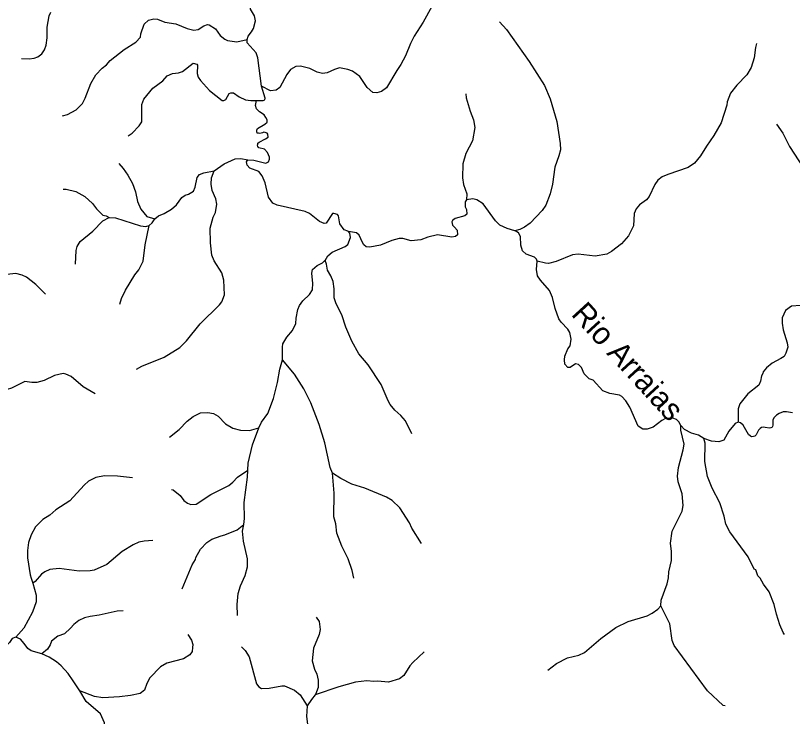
# Model space of a CAD drawing. Extents: x 500 to 555.2, y 9115.7 to 9171.
# Drawn here: x 511.43 to 518.44, y 9120.08 to 9126.41 of the extents above; entities that cross this region are included whole.
import ezdxf
from ezdxf.enums import TextEntityAlignment as Align

# ---------------------------------------------------------------- set-up
doc = ezdxf.new("R2010")
doc.units = 0
doc.header["$LTSCALE"] = 0.064
doc.layers.add('61', color=7, linetype='Continuous')
doc.layers.add('7', color=7, linetype='Continuous', lineweight=25)

msp = doc.modelspace()

# ---------------------------------------------------------------- linework, layer by layer
at = {"layer": '7'}
for points in [[(513.5153, 9126.1907), (513.524, 9126.2197), (513.5567, 9126.2587), (513.5731, 9126.2883), (513.5911, 9126.3571), (513.5813, 9126.403), (513.5472, 9126.4633), (513.5455, 9126.498), (513.5603, 9126.5225), (513.5851, 9126.5309), (513.639, 9126.5082), (513.6725, 9126.511), (513.6954, 9126.5417), (513.707, 9126.578)], [(515.1839, 9126.4888), (515.105, 9126.3473), (515.0234, 9126.2198), (514.9899, 9126.1526), (514.9459, 9126.0422), (514.9049, 9125.9635), (514.8666, 9125.9091), (514.7738, 9125.7535), (514.729, 9125.7221), (514.6854, 9125.7091), (514.6515, 9125.7124), (514.5984, 9125.7555), (514.5325, 9125.8567), (514.4663, 9125.9029), (514.4238, 9125.9193), (514.3503, 9125.9334), (514.3057, 9125.9205), (514.2375, 9125.8881), (514.1961, 9125.8847), (514.1494, 9125.8961), (514.0818, 9125.9294), (513.9985, 9125.9501), (513.9571, 9125.9453), (513.9078, 9125.9192), (513.8736, 9125.8749), (513.811, 9125.7568), (513.7769, 9125.734), (513.7276, 9125.7275), (513.6466, 9125.7683)], [(511.4793, 9126.0192), (511.5479, 9126.0143), (511.5926, 9126.0206), (511.6256, 9126.0337), (511.6621, 9126.0619), (511.6867, 9126.0955), (511.7029, 9126.1402), (511.7113, 9126.2062), (511.7098, 9126.3008), (511.7301, 9126.4028), (511.744, 9126.4358)], [(511.8491, 9125.5007), (511.8952, 9125.5134), (511.9728, 9125.5544), (512.0291, 9125.612), (512.0555, 9125.6611), (512.1049, 9125.7923), (512.1494, 9125.8716), (512.2079, 9125.9318), (512.2479, 9125.962), (512.279, 9126.001), (512.4076, 9126.1005), (512.5121, 9126.1658), (512.5544, 9126.2119), (512.5579, 9126.2423), (512.586, 9126.3291), (512.6273, 9126.3638), (512.6754, 9126.3751), (512.7075, 9126.3721), (512.7737, 9126.3474), (512.8739, 9126.3322), (512.9748, 9126.2887), (513.034, 9126.2751), (513.0738, 9126.2804), (513.1265, 9126.3133), (513.1576, 9126.324), (513.1745, 9126.3225), (513.2292, 9126.2873), (513.2734, 9126.2256), (513.314, 9126.1925), (513.3386, 9126.1801), (513.4219, 9126.1701), (513.5153, 9126.1907)], [(515.7935, 9126.3494), (515.8576, 9126.2788), (516.0617, 9125.9924), (516.1991, 9125.7748), (516.2525, 9125.6558), (516.3109, 9125.451), (516.3404, 9125.2522), (516.3434, 9125.1959), (516.331, 9125.1393), (516.2942, 9125.0377), (516.2716, 9124.8856), (516.2501, 9124.7962), (516.2125, 9124.6961), (516.1785, 9124.6468), (516.0701, 9124.5338), (516.0207, 9124.4955), (515.9786, 9124.4752), (515.9329, 9124.4649)], [(513.6466, 9125.7683), (513.6142, 9126.0251), (513.5971, 9126.0689), (513.5179, 9126.1597), (513.5153, 9126.1907)], [(518.1147, 9126.1532), (518.1045, 9126.1172), (518.0936, 9126.0252), (518.0664, 9125.9382), (518.0268, 9125.8704), (517.9353, 9125.7787), (517.8776, 9125.7047), (517.848, 9125.6261), (517.8459, 9125.5988), (517.7951, 9125.4386), (517.7296, 9125.3238), (517.6624, 9125.2286), (517.6097, 9125.1389), (517.5529, 9125.0732), (517.4955, 9125.0338), (517.314, 9124.9724), (517.2632, 9124.9494), (517.2244, 9124.9218), (517.1971, 9124.8819), (517.1452, 9124.7737), (517.121, 9124.7431), (517.0575, 9124.6975), (517.0274, 9124.6627), (517.0093, 9124.6204), (517.0028, 9124.5091), (516.9574, 9124.4188), (516.8963, 9124.3461), (516.8053, 9124.2761), (516.7635, 9124.2543), (516.6571, 9124.2346), (516.5035, 9124.2525), (516.4542, 9124.2464), (516.3064, 9124.1861), (516.2367, 9124.1691), (516.2084, 9124.1708), (516.1328, 9124.1909)], [(512.4426, 9125.3219), (512.4792, 9125.3455), (512.543, 9125.4107), (512.5658, 9125.4474), (512.5664, 9125.6036), (512.5851, 9125.6504), (512.6645, 9125.75), (512.7538, 9125.8166), (512.7958, 9125.8614), (512.8424, 9125.8818), (512.8963, 9125.8881), (512.9328, 9125.9008), (513.029, 9125.9761), (513.0608, 9125.9682), (513.0691, 9125.9587), (513.0666, 9125.8827), (513.0744, 9125.8493), (513.0951, 9125.8188), (513.1762, 9125.7306), (513.2906, 9125.6406), (513.3063, 9125.6402), (513.3242, 9125.6481), (513.3536, 9125.7038), (513.3701, 9125.7093), (513.3927, 9125.7076), (513.4441, 9125.6728), (513.502, 9125.6455), (513.5493, 9125.6381), (513.5999, 9125.6402)], [(513.5999, 9125.6402), (513.6612, 9125.6388), (513.6745, 9125.6455), (513.6802, 9125.6592), (513.6466, 9125.7683)], [(513.5233, 9125.1055), (513.5772, 9125.1018), (513.6856, 9125.0745), (513.7076, 9125.0862), (513.719, 9125.1102), (513.7172, 9125.129), (513.7008, 9125.1711), (513.6719, 9125.2002), (513.6222, 9125.2134), (513.6126, 9125.2244), (513.6097, 9125.2354), (513.6113, 9125.2455), (513.6139, 9125.2542), (513.6241, 9125.2645), (513.6824, 9125.2923), (513.706, 9125.3102), (513.7042, 9125.3364), (513.6955, 9125.3463), (513.6803, 9125.3512), (513.6673, 9125.353), (513.6536, 9125.3473), (513.6306, 9125.3431), (513.6191, 9125.3452), (513.6076, 9125.3463), (513.6043, 9125.3573), (513.6034, 9125.3724), (513.6111, 9125.3858), (513.6759, 9125.4248), (513.6961, 9125.4443), (513.6977, 9125.4657), (513.685, 9125.4865), (513.6693, 9125.5094), (513.6269, 9125.536), (513.6011, 9125.5652), (513.5915, 9125.5951), (513.5999, 9125.6402)], [(515.4895, 9125.6995), (515.494, 9125.6632), (515.5285, 9125.543), (515.5596, 9125.4643), (515.571, 9125.3956), (515.5494, 9125.276), (515.4909, 9125.1618), (515.463, 9125.0671), (515.4592, 9124.9422), (515.4693, 9124.8814), (515.5, 9124.7968), (515.4966, 9124.7429)], [(518.2954, 9125.4274), (518.3529, 9125.3434), (518.4123, 9125.2248), (518.5337, 9125.0361), (518.5639, 9124.9804), (518.5778, 9124.9196), (518.6115, 9124.8383), (518.6578, 9124.6847), (518.7217, 9124.5403), (518.7361, 9124.4723), (518.7348, 9124.3947), (518.7102, 9124.3225), (518.6475, 9124.2163), (518.5854, 9124.1454), (518.558, 9124.1033), (518.5447, 9124.0699), (518.535, 9123.9662), (518.543, 9123.8919), (518.5349, 9123.8409), (518.5111, 9123.7887)], [(513.2176, 9125.006), (513.3091, 9125.0695), (513.4079, 9125.1122), (513.4607, 9125.1172), (513.5233, 9125.1055)], [(514.4318, 9124.4585), (514.4262, 9124.4595), (514.3933, 9124.4727), (514.3522, 9124.5271), (514.3423, 9124.5996), (514.3319, 9124.6118), (514.2998, 9124.6214), (514.2875, 9124.6191), (514.228, 9124.5338), (514.2117, 9124.5302), (514.1699, 9124.5488), (514.0797, 9124.6191), (514.0412, 9124.6394), (513.7862, 9124.6951), (513.7482, 9124.7125), (513.7095, 9124.7659), (513.6793, 9124.8954), (513.6533, 9124.9596), (513.6221, 9125.0004), (513.5393, 9125.03), (513.516, 9125.0547), (513.5116, 9125.0867), (513.5233, 9125.1055)], [(512.3579, 9125.0696), (512.3967, 9125.027), (512.4403, 9124.9651), (512.4811, 9124.8913), (512.5084, 9124.8152), (512.5266, 9124.7272), (512.5575, 9124.6583), (512.6098, 9124.5943), (512.6824, 9124.5705)], [(512.5174, 9123.2153), (512.5667, 9123.2408), (512.7677, 9123.3243), (512.91, 9123.4108), (512.9682, 9123.4707), (513.0921, 9123.6239), (513.2667, 9123.7954), (513.2878, 9123.8218), (513.3122, 9123.8869), (513.3072, 9124.0186), (513.2876, 9124.0836), (513.2186, 9124.1941), (513.1976, 9124.243), (513.1844, 9124.3546), (513.1828, 9124.4866), (513.21, 9124.5869), (513.2302, 9124.6299), (513.2418, 9124.7037), (513.2332, 9124.7515), (513.1998, 9124.8262), (513.191, 9124.8861), (513.1958, 9124.9426), (513.2176, 9125.006)], [(512.6824, 9124.5705), (512.6831, 9124.5716), (512.7152, 9124.5996), (512.7661, 9124.6202), (512.8345, 9124.6603), (512.8787, 9124.6983), (512.9274, 9124.7631), (512.958, 9124.7839), (512.9874, 9124.7956), (513.0311, 9124.8203), (513.0482, 9124.8569), (513.0645, 9124.9437), (513.0852, 9124.9712), (513.1246, 9124.988), (513.2176, 9125.006)], [(511.8562, 9124.8381), (511.8831, 9124.8406), (511.97, 9124.817), (512.0505, 9124.7735), (512.1194, 9124.7107), (512.1552, 9124.6633), (512.2144, 9124.6059), (512.2437, 9124.5999), (512.2716, 9124.5829)], [(515.4966, 9124.7429), (515.4842, 9124.7265), (515.4841, 9124.6786), (515.4961, 9124.655), (515.4996, 9124.6143), (515.4826, 9124.5999), (515.3929, 9124.5758), (515.3701, 9124.5562), (515.3644, 9124.5438), (515.3685, 9124.5151), (515.3866, 9124.4952), (515.4134, 9124.4684), (515.415, 9124.4288), (515.3981, 9124.4132), (515.363, 9124.4053), (515.2335, 9124.4281), (515.1476, 9124.4056), (515.0832, 9124.382), (514.9964, 9124.3726), (514.9205, 9124.3951), (514.8877, 9124.3953), (514.8208, 9124.3771), (514.7202, 9124.3354), (514.6245, 9124.3151), (514.5918, 9124.3201), (514.5689, 9124.3364), (514.5588, 9124.3575), (514.5269, 9124.4244), (514.5032, 9124.4457), (514.4318, 9124.4585)], [(515.9329, 9124.4649), (515.8622, 9124.4853), (515.7983, 9124.5146), (515.7592, 9124.555), (515.6452, 9124.7062), (515.5903, 9124.7438), (515.5529, 9124.7511), (515.4976, 9124.7442), (515.4966, 9124.7429)], [(511.9672, 9124.1613), (511.9724, 9124.2851), (511.9816, 9124.3219), (512.0104, 9124.3678), (512.1221, 9124.4601), (512.2144, 9124.5523), (512.2716, 9124.5829)], [(512.2716, 9124.5829), (512.3281, 9124.5805), (512.5525, 9124.5099), (512.6032, 9124.5036), (512.6305, 9124.5109)], [(512.3656, 9123.8003), (512.3809, 9123.8528), (512.4181, 9123.929), (512.5018, 9124.0667), (512.5376, 9124.1128), (512.5767, 9124.19), (512.5959, 9124.3357), (512.6305, 9124.5109)], [(512.6305, 9124.5109), (512.6592, 9124.5351), (512.6824, 9124.5705)], [(514.2196, 9124.1956), (514.2458, 9124.2377), (514.2829, 9124.2719), (514.4014, 9124.3232), (514.4263, 9124.3389), (514.4491, 9124.4038), (514.4428, 9124.443), (514.4318, 9124.4585)], [(516.1328, 9124.1909), (516.1285, 9124.2075), (516.1088, 9124.2273), (516.0346, 9124.2534), (516.0026, 9124.2839), (515.9852, 9124.3347), (515.9837, 9124.4117), (515.9655, 9124.4451), (515.9364, 9124.4639), (515.9329, 9124.4649)], [(513.8348, 9123.2985), (513.834, 9123.4144), (513.8392, 9123.4445), (513.8746, 9123.5025), (513.9253, 9123.5648), (513.9568, 9123.6276), (513.9586, 9123.6746), (513.9748, 9123.755), (513.9883, 9123.7883), (514.0189, 9123.8323), (514.0795, 9123.8897), (514.1062, 9123.9319), (514.1094, 9123.99), (514.1014, 9124.0778), (514.1017, 9124.1005), (514.1075, 9124.1154), (514.1477, 9124.1501), (514.197, 9124.176), (514.2189, 9124.1944), (514.2196, 9124.1956)], [(515.0032, 9122.6327), (514.9444, 9122.7484), (514.9037, 9122.7972), (514.85, 9122.8446), (514.8071, 9122.8957), (514.7881, 9122.9301), (514.7274, 9123.077), (514.609, 9123.2548), (514.5258, 9123.3526), (514.4605, 9123.4668), (514.4075, 9123.5952), (514.3716, 9123.7069), (514.3192, 9123.8043), (514.3031, 9123.8579), (514.3014, 9123.9393), (514.2913, 9124.0055), (514.2718, 9124.0573), (514.242, 9124.108), (514.2338, 9124.1631), (514.2196, 9124.1956)], [(516.4289, 9123.545), (516.4098, 9123.5763), (516.3498, 9123.6381), (516.3308, 9123.6697), (516.2965, 9123.764), (516.2718, 9123.8624), (516.2467, 9123.9262), (516.1649, 9124.0197), (516.1384, 9124.0581), (516.1271, 9124.1158), (516.1328, 9124.1909)], [(511.6973, 9123.8926), (511.608, 9123.9803), (511.5244, 9124.0459), (511.4844, 9124.0641), (511.4273, 9124.0784), (511.2921, 9124.0624), (511.2582, 9124.0441), (511.2088, 9124.0295), (511.0656, 9124.0278), (511.0514, 9124.0214), (510.9935, 9124.0149), (510.9343, 9123.9871), (510.8076, 9123.8737), (510.708, 9123.8142), (510.6315, 9123.795), (510.494, 9123.8064)], [(518.5111, 9123.7887), (518.4311, 9123.7832), (518.3759, 9123.744), (518.3466, 9123.6789), (518.3464, 9123.6303), (518.3547, 9123.5713), (518.3905, 9123.4538), (518.3955, 9123.4133), (518.3902, 9123.3943), (518.379, 9123.3606), (518.3626, 9123.331), (518.3326, 9123.3126), (518.2556, 9123.2696), (518.2037, 9123.2258), (518.1737, 9123.1926), (518.1704, 9123.1762), (518.1578, 9123.1562), (518.1511, 9123.1067), (518.1358, 9123.0712), (518.0351, 9122.9932), (517.9635, 9122.9023), (517.9494, 9122.8585), (517.9484, 9122.7369)], [(517.4296, 9122.7079), (517.4139, 9122.7394), (517.3916, 9122.7598), (517.3578, 9122.7728), (517.2917, 9122.7697), (517.2589, 9122.7533), (517.1801, 9122.6927), (517.1267, 9122.6735), (517.0873, 9122.6734), (517.0444, 9122.7022), (516.9705, 9122.8726), (516.9334, 9122.9293), (516.8968, 9122.9677), (516.8776, 9122.9798), (516.7897, 9122.9962), (516.7259, 9123.0209), (516.64, 9123.1147), (516.604, 9123.1295), (516.5571, 9123.1736), (516.5337, 9123.2307), (516.5074, 9123.2583), (516.4814, 9123.2632), (516.4326, 9123.2312), (516.4122, 9123.2307), (516.3824, 9123.2591), (516.3797, 9123.2996), (516.3846, 9123.3318), (516.4122, 9123.3974), (516.4317, 9123.427), (516.4403, 9123.4867), (516.4289, 9123.545)], [(513.6203, 9122.6864), (513.6448, 9122.7367), (513.7024, 9122.8159), (513.7552, 9122.9493), (513.7911, 9123.0956), (513.811, 9123.2144), (513.8348, 9123.2985)], [(514.2875, 9122.278), (514.2667, 9122.3285), (514.2163, 9122.551), (514.1667, 9122.7163), (514.0897, 9122.9125), (514.0266, 9123.039), (513.9442, 9123.1711), (513.8348, 9123.2985)], [(512.1454, 9122.9926), (512.0366, 9123.0549), (511.9279, 9123.1485), (511.8787, 9123.1715), (511.8562, 9123.1748), (511.7764, 9123.1583), (511.6845, 9123.1124), (511.6176, 9123.0948), (511.5739, 9123.0942), (511.5081, 9123.1026), (511.3905, 9123.0423), (511.3505, 9123.0323), (511.2909, 9123.029), (511.2141, 9123.0353), (511.1006, 9123.0815), (511.0304, 9123.0942), (510.9831, 9123.1141), (510.9346, 9123.1223)], [(518.4392, 9122.8223), (518.3834, 9122.8299), (518.3541, 9122.8288), (518.3173, 9122.8155), (518.2956, 9122.7992), (518.2743, 9122.7805), (518.261, 9122.7584), (518.2609, 9122.7113), (518.2585, 9122.6986), (518.256, 9122.6923), (518.2525, 9122.6882), (518.2442, 9122.6848), (518.2304, 9122.6838), (518.1906, 9122.6894), (518.1732, 9122.6907), (518.1598, 9122.6877), (518.148, 9122.6811), (518.1318, 9122.6636), (518.1105, 9122.6231), (518.099, 9122.6106), (518.0863, 9122.6068), (518.0725, 9122.6044), (518.0582, 9122.6093), (518.0408, 9122.6251), (517.9942, 9122.7108), (517.9695, 9122.7311), (517.9484, 9122.7369)], [(512.8164, 9122.6003), (512.9025, 9122.67), (512.9756, 9122.7447), (513.0285, 9122.7894), (513.0955, 9122.8222), (513.162, 9122.8239), (513.2138, 9122.8141), (513.2532, 9122.7911), (513.3207, 9122.7219), (513.3881, 9122.6839), (513.4554, 9122.6652), (513.5382, 9122.6616), (513.6203, 9122.6864)], [(513.5227, 9122.3037), (513.5265, 9122.3668), (513.5632, 9122.5313), (513.6203, 9122.6864)], [(517.2498, 9121.0795), (517.2542, 9121.1299), (517.3078, 9121.2781), (517.3196, 9121.3319), (517.3235, 9121.3876), (517.3456, 9121.4873), (517.3458, 9121.5688), (517.336, 9121.6462), (517.3513, 9121.7525), (517.4419, 9121.9336), (517.4519, 9121.9835), (517.4414, 9122.0899), (517.4065, 9122.1973), (517.4016, 9122.2484), (517.4083, 9122.3292), (517.4523, 9122.4861), (517.4605, 9122.5379), (517.4301, 9122.6658), (517.4296, 9122.7079)], [(517.639, 9122.5893), (517.5905, 9122.6185), (517.5285, 9122.6367), (517.4625, 9122.67), (517.4296, 9122.7079)], [(517.9484, 9122.7369), (517.9211, 9122.7237), (517.8631, 9122.6559), (517.8192, 9122.5742), (517.7733, 9122.5582), (517.7083, 9122.5648), (517.639, 9122.5893)], [(518.3675, 9120.8214), (518.3544, 9120.8389), (518.3241, 9120.9068), (518.2939, 9121.0032), (518.2743, 9121.0913), (518.2269, 9121.2061), (518.1771, 9121.2744), (518.1462, 9121.328), (518.1267, 9121.3494), (518.1068, 9121.403), (518.0939, 9121.4107), (518.0373, 9121.5227), (517.8718, 9121.7462), (517.836, 9121.8174), (517.8208, 9121.888), (517.7837, 9122.0103), (517.7133, 9122.1416), (517.6706, 9122.2465), (517.6461, 9122.383), (517.6492, 9122.5477), (517.639, 9122.5893)], [(512.832, 9122.1287), (512.848, 9122.127), (512.9107, 9122.0755), (512.9455, 9122.0293), (512.9773, 9122.0052), (513.0092, 9121.9953), (513.0552, 9121.997), (513.1887, 9122.0854), (513.351, 9122.1662), (513.3885, 9122.1947), (513.4301, 9122.2396), (513.5227, 9122.3037)], [(513.4864, 9121.8126), (513.4914, 9121.868), (513.4899, 9122.0107), (513.5189, 9122.2401), (513.5227, 9122.3037)], [(515.0905, 9121.6419), (515.0028, 9121.7819), (514.9803, 9121.8299), (514.8931, 9121.9632), (514.8241, 9122.0304), (514.7749, 9122.0614), (514.5792, 9122.1429), (514.4626, 9122.1782), (514.361, 9122.2292), (514.2875, 9122.278)], [(514.4781, 9121.3282), (514.4635, 9121.398), (514.4293, 9121.5051), (514.3707, 9121.6194), (514.3244, 9121.7348), (514.3159, 9121.8181), (514.2998, 9121.8824), (514.3014, 9122.0962), (514.2875, 9122.278)], [(512.4814, 9122.2356), (512.3458, 9122.2497), (512.2297, 9122.2531), (512.151, 9122.2366), (512.0855, 9122.2038), (512.0456, 9122.169), (511.9147, 9122.0284), (511.7894, 9121.9453), (511.7364, 9121.8975), (511.6716, 9121.8574), (511.6065, 9121.7922), (511.5673, 9121.7205), (511.5437, 9121.6498), (511.5343, 9121.5786), (511.5342, 9121.5138), (511.5568, 9121.359), (511.5656, 9121.3282), (511.5824, 9121.2839)], [(512.9299, 9121.232), (513.0188, 9121.4492), (513.0495, 9121.4987), (513.0532, 9121.5164), (513.0966, 9121.5914), (513.1523, 9121.6517), (513.1987, 9121.6811), (513.2807, 9121.7121), (513.3134, 9121.7189), (513.4265, 9121.7657), (513.4864, 9121.8126)], [(513.4294, 9120.992), (513.4256, 9121.0931), (513.4354, 9121.1895), (513.4561, 9121.2587), (513.4988, 9121.353), (513.5197, 9121.4318), (513.5203, 9121.504), (513.4832, 9121.6639), (513.4747, 9121.7534), (513.4864, 9121.8126)], [(512.6661, 9121.6692), (512.5879, 9121.6627), (512.5387, 9121.6528), (512.4884, 9121.6311), (512.3868, 9121.5712), (512.2511, 9121.4528), (512.1342, 9121.4028), (512.0985, 9121.3954), (511.9996, 9121.3936), (511.8196, 9121.4165), (511.7356, 9121.4069), (511.6899, 9121.3878), (511.6592, 9121.3661), (511.6014, 9121.2985), (511.5824, 9121.2839)], [(511.5824, 9121.2839), (511.6128, 9121.1745), (511.6128, 9121.1148), (511.5801, 9121.023), (511.4995, 9120.8776), (511.4289, 9120.7954)], [(516.2291, 9120.4982), (516.3084, 9120.559), (516.4087, 9120.6098), (516.509, 9120.6351), (516.5601, 9120.6588), (516.7088, 9120.7858), (516.845, 9120.8847), (516.9565, 9120.9373), (517.1255, 9120.9906), (517.1735, 9121.0131), (517.2227, 9121.0491), (517.2498, 9121.0795)], [(517.831, 9120.176), (517.8121, 9120.1817), (517.6715, 9120.3133), (517.3701, 9120.7217), (517.3531, 9120.7661), (517.3307, 9120.9185), (517.2498, 9121.0795)], [(512.3975, 9121.0359), (512.3418, 9121.0328), (512.1811, 9120.9952), (512.1, 9120.9847), (512.0475, 9120.9714), (511.9983, 9120.9482), (511.9505, 9120.911), (511.9221, 9120.8776), (511.8665, 9120.8272), (511.8073, 9120.8071), (511.7491, 9120.7613), (511.7375, 9120.7292), (511.7139, 9120.6897), (511.6644, 9120.6457)], [(514.1395, 9120.9772), (514.1652, 9120.9376), (514.1767, 9120.8659), (514.167, 9120.8201), (514.1148, 9120.6991), (514.1046, 9120.5838), (514.1228, 9120.5079), (514.1455, 9120.4619), (514.1586, 9120.4078), (514.1586, 9120.3419), (514.133, 9120.2781), (514.1308, 9120.2753)], [(511.4289, 9120.7954), (511.3955, 9120.7857), (511.3714, 9120.7477), (511.3286, 9120.7041), (511.2815, 9120.6934), (511.2808, 9120.6937)], [(511.6644, 9120.6457), (511.5681, 9120.6735), (511.536, 9120.6939), (511.5047, 9120.7407), (511.4706, 9120.7796), (511.4289, 9120.7954)], [(512.9821, 9120.8198), (513.0152, 9120.7708), (513.0252, 9120.7315), (513.024, 9120.7032), (513.0186, 9120.6681), (513, 9120.6384), (512.9421, 9120.6016), (512.7913, 9120.562), (512.7328, 9120.5304), (512.639, 9120.4298), (512.611, 9120.3785), (512.5885, 9120.3172), (512.5517, 9120.2899), (512.4648, 9120.2699), (512.3627, 9120.257), (512.2127, 9120.2504), (512.1396, 9120.2622), (512.0049, 9120.3117)], [(513.4664, 9120.71), (513.4995, 9120.6763), (513.5334, 9120.6199), (513.6014, 9120.3751), (513.6227, 9120.3474), (513.6466, 9120.3326), (513.7153, 9120.3356), (513.8301, 9120.3585), (513.8547, 9120.3585), (513.9443, 9120.3189), (513.9942, 9120.2769), (514.0573, 9120.1773)], [(515.1128, 9120.6639), (515.0112, 9120.5697), (514.9845, 9120.5368), (514.9304, 9120.4499), (514.8903, 9120.4212), (514.7912, 9120.3898), (514.694, 9120.4011), (514.6601, 9120.398), (514.5957, 9120.4027), (514.4954, 9120.3895), (514.343, 9120.3488), (514.1308, 9120.2753)], [(512.0049, 9120.3117), (511.9468, 9120.4039), (511.8996, 9120.469), (511.8382, 9120.5384), (511.7956, 9120.573), (511.7284, 9120.6157), (511.6644, 9120.6457)], [(512.2326, 9119.8378), (512.2315, 9119.8409), (512.2284, 9119.895), (512.2345, 9119.9738), (512.2282, 9120.025), (512.1928, 9120.1064), (512.0641, 9120.2176), (512.0049, 9120.3117)], [(514.1308, 9120.2753), (514.0972, 9120.2358), (514.0573, 9120.1773)], [(514.0573, 9120.1773), (514.0505, 9120.0813), (514.0617, 9120.013), (514.027, 9119.9245), (514.0194, 9119.8681), (514.0308, 9119.7631), (514.0963, 9119.5263), (514.0979, 9119.4706), (514.07, 9119.3663), (514.0244, 9119.288), (514.004, 9119.2657), (513.8694, 9119.1822), (513.7913, 9119.1612), (513.6266, 9119.1759), (513.5294, 9119.1237), (513.4567, 9119.1032)]]:
    msp.add_lwpolyline(points, dxfattribs=at)

# ---------------------------------------------------------------- texts
at = {"layer": '61'}
msp.add_text('Rio Arraias', height=0.2, rotation=312.51, dxfattribs=at).set_placement((516.8804, 9123.2185), align=Align.CENTER)

doc.saveas('drawing.dxf')
